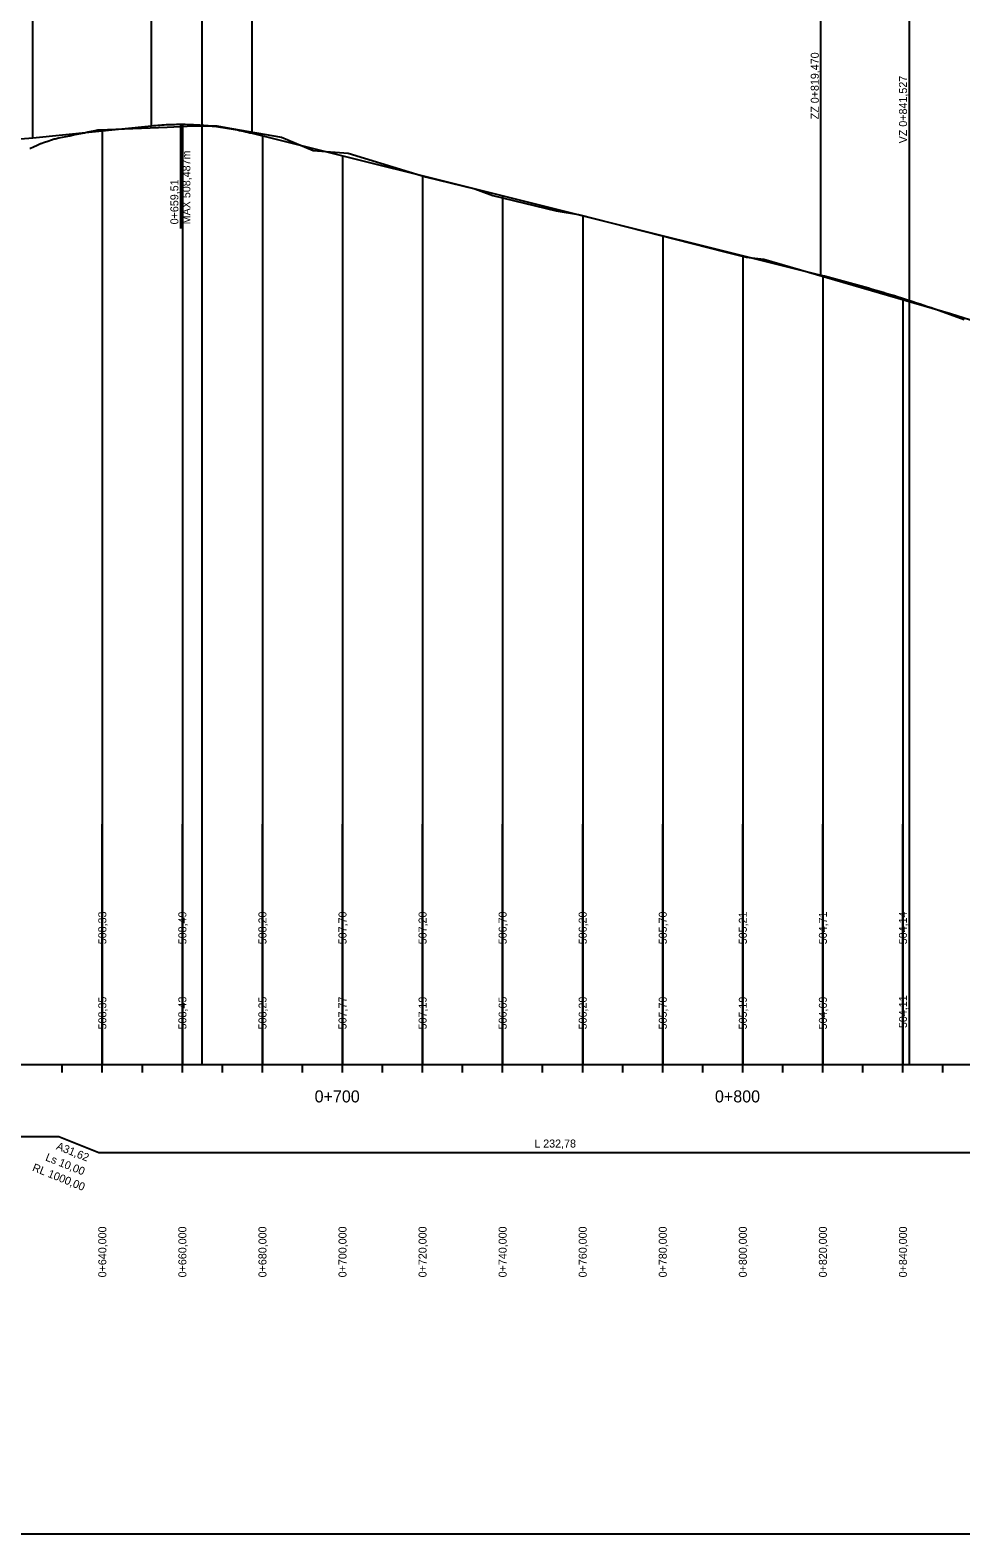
# Model space of a CAD drawing. Extents: x -632716 to -629545, y -1094726 to -1088285.
# Drawn here: x -631988.8 to -631756.3, y -1093689.1 to -1093313.3 of the extents above; entities that cross this region are included whole.
import ezdxf

# ---------------------------------------------------------------- set-up
doc = ezdxf.new("R2010")
doc.units = 0
for name, color, linetype in [('20', 7, 'Continuous'), ('Default', 7, 'Continuous'), ('formát', 7, 'Continuous'), ('NIVELETA_VYSKY', 7, 'Continuous'), ('REZ_POPIS', 7, 'Continuous'), ('REZ_TABULKA', 7, 'Continuous'), ('REZ_TENKA', 7, 'Continuous'), ('REZ_TLUSTA', 7, 'Continuous'), ('SKLONY_NIVELETA', 7, 'Continuous'), ('SKLONY_POPIS', 7, 'Continuous'), ('TECNY_NIVELETA', 7, 'Continuous'), ('TEREN_VYSKY', 7, 'Continuous'), ('VOZOVKA', 7, 'Continuous')]:
    doc.layers.add(name, color=color, linetype=linetype)

msp = doc.modelspace()

# ---------------------------------------------------------------- linework, layer by layer
at = {"layer": '20'}
for points in [[(-631970.75, -1093338.46), (-631970.75, -1093521.74), (-631970.75, -1093571.74), (-631970.75, -1093511.74)], [(-631950.75, -1093336.86), (-631950.75, -1093521.74), (-631950.75, -1093571.74), (-631950.75, -1093511.74)], [(-631930.75, -1093339.74), (-631930.75, -1093521.74), (-631930.75, -1093571.74), (-631930.75, -1093511.74)], [(-631910.75, -1093344.73), (-631910.75, -1093521.74), (-631910.75, -1093571.74), (-631910.75, -1093511.74)], [(-631890.75, -1093349.72), (-631890.75, -1093521.74), (-631890.75, -1093571.74), (-631890.75, -1093511.74)], [(-631870.75, -1093354.71), (-631870.75, -1093521.74), (-631870.75, -1093571.74), (-631870.75, -1093511.74)], [(-631850.75, -1093359.7), (-631850.75, -1093521.74), (-631850.75, -1093571.74), (-631850.75, -1093511.74)], [(-631830.75, -1093364.69), (-631830.75, -1093521.74), (-631830.75, -1093571.74), (-631830.75, -1093511.74)], [(-631810.75, -1093369.68), (-631810.75, -1093521.74), (-631810.75, -1093571.74), (-631810.75, -1093511.74)], [(-631790.75, -1093374.67), (-631790.75, -1093521.74), (-631790.75, -1093571.74), (-631790.75, -1093511.74)], [(-631770.75, -1093380.35), (-631770.75, -1093521.74), (-631770.75, -1093571.74), (-631770.75, -1093511.74)]]:
    msp.add_lwpolyline(points, dxfattribs=at)
at = {"layer": 'Default'}
for p, q in [((-631988.1, -1093340.21), (-631958.46, -1093337.23)), ((-631988.1, -1093340.21), (-631958.46, -1093337.23)), ((-631933.35, -1093339.1), (-631791.28, -1093374.53)), ((-631933.35, -1093339.1), (-631791.28, -1093374.53))]:
    msp.add_line(p, q, dxfattribs=at)
for points in [[(-631958.46, -1093337.23), (-631957.94, -1093337.18), (-631957.42, -1093337.13), (-631956.9, -1093337.09), (-631956.37, -1093337.05), (-631955.85, -1093337.01), (-631955.33, -1093336.98), (-631954.8, -1093336.95), (-631954.28, -1093336.93), (-631953.76, -1093336.91), (-631953.23, -1093336.89), (-631952.71, -1093336.88), (-631952.19, -1093336.87), (-631951.66, -1093336.86), (-631951.14, -1093336.86), (-631950.62, -1093336.87), (-631950.09, -1093336.87), (-631949.57, -1093336.88), (-631949.05, -1093336.9), (-631948.52, -1093336.91), (-631948, -1093336.94), (-631947.48, -1093336.96), (-631946.95, -1093336.99), (-631946.43, -1093337.02), (-631945.38, -1093337.1), (-631944.86, -1093337.15), (-631944.34, -1093337.2), (-631943.82, -1093337.25), (-631943.29, -1093337.3), (-631942.77, -1093337.36), (-631942.25, -1093337.43), (-631941.72, -1093337.5), (-631941.2, -1093337.57), (-631940.68, -1093337.64), (-631940.15, -1093337.72), (-631939.63, -1093337.8), (-631939.11, -1093337.89), (-631938.58, -1093337.98), (-631938.06, -1093338.07), (-631937.54, -1093338.17), (-631937.01, -1093338.27), (-631936.49, -1093338.38), (-631935.97, -1093338.49), (-631935.44, -1093338.6), (-631934.92, -1093338.72), (-631934.4, -1093338.84), (-631933.87, -1093338.97), (-631933.35, -1093339.1)], [(-631958.46, -1093337.23), (-631957.94, -1093337.18), (-631957.42, -1093337.13), (-631956.9, -1093337.09), (-631956.37, -1093337.05), (-631955.85, -1093337.01), (-631955.33, -1093336.98), (-631954.8, -1093336.95), (-631954.28, -1093336.93), (-631953.76, -1093336.91), (-631953.23, -1093336.89), (-631952.71, -1093336.88), (-631952.19, -1093336.87), (-631951.66, -1093336.86), (-631951.14, -1093336.86), (-631950.62, -1093336.87), (-631950.09, -1093336.87), (-631949.57, -1093336.88), (-631949.05, -1093336.9), (-631948.52, -1093336.91), (-631948, -1093336.94), (-631947.48, -1093336.96), (-631946.95, -1093336.99), (-631946.43, -1093337.02), (-631945.38, -1093337.1), (-631944.86, -1093337.15), (-631944.34, -1093337.2), (-631943.82, -1093337.25), (-631943.29, -1093337.3), (-631942.77, -1093337.36), (-631942.25, -1093337.43), (-631941.72, -1093337.5), (-631941.2, -1093337.57), (-631940.68, -1093337.64), (-631940.15, -1093337.72), (-631939.63, -1093337.8), (-631939.11, -1093337.89), (-631938.58, -1093337.98), (-631938.06, -1093338.07), (-631937.54, -1093338.17), (-631937.01, -1093338.27), (-631936.49, -1093338.38), (-631935.97, -1093338.49), (-631935.44, -1093338.6), (-631934.92, -1093338.72), (-631934.4, -1093338.84), (-631933.87, -1093338.97), (-631933.35, -1093339.1)], [(-631991.19, -1093340.51), (-631988.1, -1093340.21)], [(-631991.19, -1093340.51), (-631988.1, -1093340.21)], [(-631791.28, -1093374.53), (-631790.36, -1093374.76), (-631789.45, -1093375), (-631788.53, -1093375.23), (-631787.61, -1093375.47), (-631786.69, -1093375.71), (-631785.77, -1093375.96), (-631784.85, -1093376.21), (-631783.93, -1093376.46), (-631783.01, -1093376.71), (-631782.09, -1093376.97), (-631781.17, -1093377.22), (-631780.26, -1093377.49), (-631779.34, -1093377.75), (-631778.42, -1093378.02), (-631777.5, -1093378.29), (-631776.58, -1093378.56), (-631775.66, -1093378.84), (-631774.74, -1093379.11), (-631773.82, -1093379.39), (-631772.9, -1093379.68), (-631771.98, -1093379.96), (-631771.07, -1093380.25), (-631770.15, -1093380.55), (-631768.31, -1093381.14), (-631767.39, -1093381.44), (-631766.47, -1093381.74), (-631765.55, -1093382.05), (-631764.63, -1093382.36), (-631763.71, -1093382.67), (-631762.79, -1093382.99), (-631761.88, -1093383.3), (-631760.96, -1093383.62), (-631760.04, -1093383.95), (-631759.12, -1093384.27), (-631758.2, -1093384.6), (-631757.28, -1093384.93), (-631756.36, -1093385.27), (-631755.44, -1093385.6)], [(-631791.28, -1093374.53), (-631790.36, -1093374.76), (-631789.45, -1093375), (-631788.53, -1093375.23), (-631787.61, -1093375.47), (-631786.69, -1093375.71), (-631785.77, -1093375.96), (-631784.85, -1093376.21), (-631783.93, -1093376.46), (-631783.01, -1093376.71), (-631782.09, -1093376.97), (-631781.17, -1093377.22), (-631780.26, -1093377.49), (-631779.34, -1093377.75), (-631778.42, -1093378.02), (-631777.5, -1093378.29), (-631776.58, -1093378.56), (-631775.66, -1093378.84), (-631774.74, -1093379.11), (-631773.82, -1093379.39), (-631772.9, -1093379.68), (-631771.98, -1093379.96), (-631771.07, -1093380.25), (-631770.15, -1093380.55), (-631768.31, -1093381.14), (-631767.39, -1093381.44), (-631766.47, -1093381.74), (-631765.55, -1093382.05), (-631764.63, -1093382.36), (-631763.71, -1093382.67), (-631762.79, -1093382.99), (-631761.88, -1093383.3), (-631760.96, -1093383.62), (-631760.04, -1093383.95), (-631759.12, -1093384.27), (-631758.2, -1093384.6), (-631757.28, -1093384.93), (-631756.36, -1093385.27), (-631755.44, -1093385.6)]]:
    msp.add_lwpolyline(points, dxfattribs=at)
at = {"layer": 'formát'}
msp.add_lwpolyline([(-632715.96, -1093689.05), (-630764.61, -1093689.05), (-630764.61, -1093095.05), (-632715.96, -1093095.05)], close=True, dxfattribs=at)
at = {"layer": 'REZ_TABULKA'}
msp.add_lwpolyline([(-632374.23, -1093593.74), (-632047.76, -1093593.74), (-632047.76, -1093593.74), (-632037.76, -1093589.74), (-632037.76, -1093589.74), (-631981.6, -1093589.74), (-631981.6, -1093589.74), (-631971.6, -1093593.74), (-631971.6, -1093593.74), (-631738.82, -1093593.74)], dxfattribs=at)
at = {"layer": 'REZ_TENKA'}
for p, q in [((-631980.75, -1093573.74), (-631980.75, -1093571.74)), ((-631970.75, -1093573.74), (-631970.75, -1093571.74)), ((-631960.75, -1093573.74), (-631960.75, -1093571.74)), ((-631950.75, -1093573.74), (-631950.75, -1093571.74)), ((-631940.75, -1093573.74), (-631940.75, -1093571.74)), ((-631930.75, -1093573.74), (-631930.75, -1093571.74)), ((-631920.75, -1093573.74), (-631920.75, -1093571.74)), ((-631900.75, -1093573.74), (-631900.75, -1093571.74)), ((-631890.75, -1093573.74), (-631890.75, -1093571.74)), ((-631880.75, -1093573.74), (-631880.75, -1093571.74)), ((-631870.75, -1093573.74), (-631870.75, -1093571.74)), ((-631860.75, -1093573.74), (-631860.75, -1093571.74)), ((-631850.75, -1093573.74), (-631850.75, -1093571.74)), ((-631840.75, -1093573.74), (-631840.75, -1093571.74)), ((-631830.75, -1093573.74), (-631830.75, -1093571.74)), ((-631820.75, -1093573.74), (-631820.75, -1093571.74)), ((-631800.75, -1093573.74), (-631800.75, -1093571.74)), ((-631790.75, -1093573.74), (-631790.75, -1093571.74)), ((-631780.75, -1093573.74), (-631780.75, -1093571.74)), ((-631770.75, -1093573.74), (-631770.75, -1093571.74)), ((-631760.75, -1093573.74), (-631760.75, -1093571.74))]:
    msp.add_line(p, q, dxfattribs=at)
at = {"layer": 'REZ_TLUSTA'}
for p, q in [((-632610.75, -1093571.74), (-631190.75, -1093571.74)), ((-631910.75, -1093573.74), (-631910.75, -1093569.74)), ((-631810.75, -1093573.74), (-631810.75, -1093569.74))]:
    msp.add_line(p, q, dxfattribs=at)
at = {"layer": 'SKLONY_NIVELETA'}
for p, q in [((-631945.91, -1093235.96), (-631945.91, -1093571.74)), ((-631769.23, -1093280.04), (-631769.23, -1093571.74)), ((-631988.1, -1093340.21), (-631958.46, -1093337.23)), ((-631933.35, -1093339.1), (-631791.28, -1093374.53))]:
    msp.add_line(p, q, dxfattribs=at)
for points in [[(-631958.46, -1093337.23), (-631957.94, -1093337.18), (-631957.42, -1093337.13), (-631956.9, -1093337.09), (-631956.37, -1093337.05), (-631955.85, -1093337.01), (-631955.33, -1093336.98), (-631954.8, -1093336.95), (-631954.28, -1093336.93), (-631953.76, -1093336.91), (-631953.23, -1093336.89), (-631952.71, -1093336.88), (-631952.19, -1093336.87), (-631951.66, -1093336.86), (-631951.14, -1093336.86), (-631950.62, -1093336.87), (-631950.09, -1093336.87), (-631949.57, -1093336.88), (-631949.05, -1093336.9), (-631948.52, -1093336.91), (-631948, -1093336.94), (-631947.48, -1093336.96), (-631946.95, -1093336.99), (-631946.43, -1093337.02), (-631945.38, -1093337.1), (-631944.86, -1093337.15), (-631944.34, -1093337.2), (-631943.82, -1093337.25), (-631943.29, -1093337.3), (-631942.77, -1093337.36), (-631942.25, -1093337.43), (-631941.72, -1093337.5), (-631941.2, -1093337.57), (-631940.68, -1093337.64), (-631940.15, -1093337.72), (-631939.63, -1093337.8), (-631939.11, -1093337.89), (-631938.58, -1093337.98), (-631938.06, -1093338.07), (-631937.54, -1093338.17), (-631937.01, -1093338.27), (-631936.49, -1093338.38), (-631935.97, -1093338.49), (-631935.44, -1093338.6), (-631934.92, -1093338.72), (-631934.4, -1093338.84), (-631933.87, -1093338.97), (-631933.35, -1093339.1)], [(-631991.19, -1093340.51), (-631988.1, -1093340.21)], [(-631791.28, -1093374.53), (-631790.36, -1093374.76), (-631789.45, -1093375), (-631788.53, -1093375.23), (-631787.61, -1093375.47), (-631786.69, -1093375.71), (-631785.77, -1093375.96), (-631784.85, -1093376.21), (-631783.93, -1093376.46), (-631783.01, -1093376.71), (-631782.09, -1093376.97), (-631781.17, -1093377.22), (-631780.26, -1093377.49), (-631779.34, -1093377.75), (-631778.42, -1093378.02), (-631777.5, -1093378.29), (-631776.58, -1093378.56), (-631775.66, -1093378.84), (-631774.74, -1093379.11), (-631773.82, -1093379.39), (-631772.9, -1093379.68), (-631771.98, -1093379.96), (-631771.07, -1093380.25), (-631770.15, -1093380.55), (-631768.31, -1093381.14), (-631767.39, -1093381.44), (-631766.47, -1093381.74), (-631765.55, -1093382.05), (-631764.63, -1093382.36), (-631763.71, -1093382.67), (-631762.79, -1093382.99), (-631761.88, -1093383.3), (-631760.96, -1093383.62), (-631760.04, -1093383.95), (-631759.12, -1093384.27), (-631758.2, -1093384.6), (-631757.28, -1093384.93), (-631756.36, -1093385.27), (-631755.44, -1093385.6)]]:
    msp.add_lwpolyline(points, dxfattribs=at)
at = {"layer": 'TECNY_NIVELETA'}
for p, q in [((-631958.46, -1093337.23), (-631958.46, -1093236.23)), ((-631988.1, -1093340.21), (-631988.1, -1093239.21)), ((-631933.35, -1093339.1), (-631933.35, -1093238.1)), ((-631791.28, -1093374.53), (-631791.28, -1093273.53)), ((-631951.25, -1093336.86), (-631951.25, -1093362.86))]:
    msp.add_line(p, q, dxfattribs=at)
at = {"layer": 'VOZOVKA'}
msp.add_lwpolyline([(-631988.85, -1093342.79), (-631988.67, -1093342.8), (-631987.95, -1093342.48), (-631987.04, -1093342.07), (-631986.21, -1093341.7), (-631986.13, -1093341.67), (-631985.23, -1093341.36), (-631984.32, -1093341.05), (-631983.42, -1093340.74), (-631982.77, -1093340.51), (-631982.51, -1093340.46), (-631981.6, -1093340.28), (-631980.7, -1093340.09), (-631979.79, -1093339.91), (-631978.88, -1093339.72), (-631977.97, -1093339.53), (-631977.06, -1093339.35), (-631976.15, -1093339.16), (-631975.24, -1093338.97), (-631974.33, -1093338.78), (-631973.42, -1093338.59), (-631972.51, -1093338.4), (-631971.88, -1093338.27), (-631971.6, -1093338.26), (-631954.53, -1093337.58), (-631947.85, -1093337.24), (-631942.17, -1093337.24), (-631938.47, -1093337.91), (-631925.97, -1093340.06), (-631918.05, -1093343.4), (-631909.36, -1093344.1), (-631890, -1093350.03), (-631877.73, -1093353.01), (-631873.23, -1093354.63), (-631857.34, -1093358.47), (-631851.78, -1093359.43), (-631815.21, -1093368.74), (-631809.95, -1093370.05), (-631805.54, -1093370.59), (-631758.84, -1093384.13), (-631750.68, -1093386.73)], dxfattribs=at)

# ---------------------------------------------------------------- texts
at = {"layer": 'NIVELETA_VYSKY'}
for s, p in [('508,33', (-631969.75, -1093541.74)), ('508,49', (-631949.75, -1093541.74)), ('508,20', (-631929.75, -1093541.74)), ('507,70', (-631909.75, -1093541.74)), ('507,20', (-631889.75, -1093541.74)), ('506,70', (-631869.75, -1093541.74)), ('506,20', (-631849.75, -1093541.74)), ('505,70', (-631829.75, -1093541.74)), ('505,21', (-631809.75, -1093541.74)), ('504,71', (-631789.75, -1093541.74)), ('504,14', (-631769.75, -1093541.74))]:
    msp.add_text(s, height=2, rotation=90, dxfattribs=at).set_placement(p)
at = {"layer": 'REZ_POPIS'}
for s, p in [('0+700', (-631917.71, -1093581.24)), ('0+800', (-631817.71, -1093581.24))]:
    msp.add_text(s, height=3, dxfattribs=at).set_placement(p)
at = {"layer": 'REZ_TABULKA'}
msp.add_text('L 232,78', height=2, dxfattribs=at).set_placement((-631862.84, -1093592.52))
for s, rotation, p in [('Ls 10,00', 338.1986, (-631985.13, -1093595.7)), ('A31,62', 338.1986, (-631982.42, -1093592.91)), ('RL 1000,00', 338.1986, (-631988.41, -1093598.26)), ('0+640,000', 90, (-631969.75, -1093624.95)), ('0+660,000', 90, (-631949.75, -1093624.95)), ('0+680,000', 90, (-631929.75, -1093624.95)), ('0+700,000', 90, (-631909.75, -1093624.95)), ('0+720,000', 90, (-631889.75, -1093624.95)), ('0+740,000', 90, (-631869.75, -1093624.95)), ('0+760,000', 90, (-631849.75, -1093624.95)), ('0+780,000', 90, (-631829.75, -1093624.95)), ('0+800,000', 90, (-631809.75, -1093624.95)), ('0+820,000', 90, (-631789.75, -1093624.95)), ('0+840,000', 90, (-631769.75, -1093624.95))]:
    msp.add_text(s, height=2, rotation=rotation, dxfattribs=at).set_placement(p)
at = {"layer": 'SKLONY_POPIS'}
for s, p in [('ZZ 0+819,470', (-631791.78, -1093335.62)), ('VZ 0+841,527', (-631769.73, -1093341.62)), ('MAX 508,487m', (-631948.75, -1093361.86)), ('0+659,51', (-631951.75, -1093361.86))]:
    msp.add_text(s, height=2, rotation=90, dxfattribs=at).set_placement(p)
at = {"layer": 'TEREN_VYSKY'}
for s, p in [('508,35', (-631969.75, -1093563)), ('508,43', (-631949.75, -1093563)), ('508,25', (-631929.75, -1093563)), ('507,77', (-631909.75, -1093563)), ('507,19', (-631889.75, -1093563)), ('506,65', (-631869.75, -1093563)), ('506,20', (-631849.75, -1093563)), ('505,70', (-631829.75, -1093563)), ('505,19', (-631809.75, -1093563)), ('504,69', (-631789.75, -1093563)), ('504,11', (-631769.75, -1093562.66))]:
    msp.add_text(s, height=2, rotation=90, dxfattribs=at).set_placement(p)

doc.saveas('drawing.dxf')
